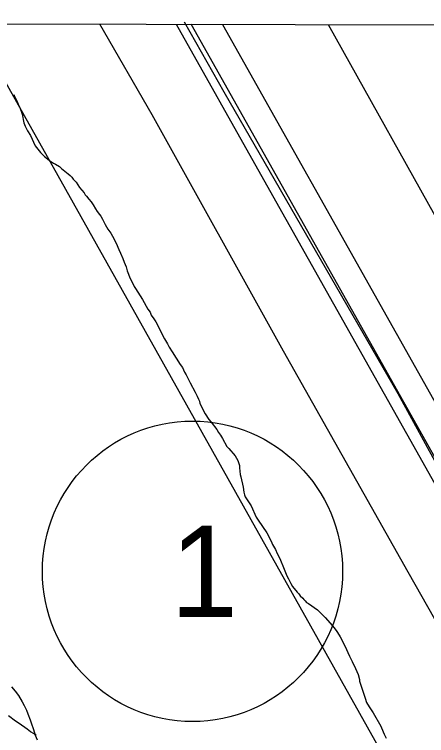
# Model space of a CAD drawing. Extents: x 3177185 to 3215018, y 812988 to 838321.
# Drawn here: x 3185862 to 3186316, y 835794 to 836586 of the extents above; entities that cross this region are included whole.
import ezdxf

# ---------------------------------------------------------------- set-up
doc = ezdxf.new("R2010")
doc.units = 0
for name, color, linetype in [('V-GRID-FRAM', 7, 'Continuous'), ('V-LEVE-TOET', 7, 'Continuous'), ('V-RAIL-TRAK', 7, 'Continuous'), ('V-ROAD-CNTR', 7, 'Continuous'), ('V-ROAD-IDEN', 7, 'Continuous'), ('V-SITE-VEGE', 7, 'Continuous'), ('V-SURV-LINE', 7, 'Continuous'), ('V-TOPO-SHOR', 7, 'Continuous'), ('V-WETL-SWMP', 7, 'Continuous')]:
    doc.layers.add(name, color=color, linetype=linetype)

msp = doc.modelspace()

# ---------------------------------------------------------------- linework, layer by layer
at = {"layer": 'V-GRID-FRAM'}
msp.add_lwpolyline([(3181402.42, 836586.07), (3212801.61, 836513), (3212767.22, 818326.14), (3181352.16, 818399.25), (3181402.42, 836586.07)], dxfattribs=at)
at = {"layer": 'V-LEVE-TOET'}
for points in [[(3187116.25, 834464.44), (3186925.6, 834825.43), (3186860.39, 834954.05), (3186855.88, 834965.58), (3186851.33, 834972.93), (3186814.33, 835039.16), (3186682.24, 835286.96), (3186507.07, 835597.19), (3186375.31, 835833.83), (3186373.07, 835840.52), (3186368.02, 835845.71), (3186295.36, 835973.65), (3186158.41, 836216.39), (3186013.75, 836475.83), (3185956.49, 836575.47)], [(3186207.54, 836574.89), (3186340.46, 836337.21), (3186539.49, 835975.81), (3186717.17, 835666.94), (3186898.65, 835340.5), (3187102.54, 834982.76), (3187266.76, 834701.36), (3187383.23, 834494.39)]]:
    msp.add_lwpolyline(points, dxfattribs=at)
at = {"layer": 'V-RAIL-TRAK'}
msp.add_lwpolyline([(3186040.17, 836575.28), (3186132.96, 836410.73), (3186321.32, 836076.29), (3186480.25, 835793.41), (3186665.13, 835465.53), (3186865.62, 835109.22), (3187040.2, 834800.55), (3187196.12, 834523.53), (3187196.25, 834523.29)], dxfattribs=at)
at = {"layer": 'V-ROAD-CNTR'}
msp.add_lwpolyline([(3186049.16, 836577.87), (3186092.78, 836501.07), (3186284.12, 836169.71), (3186468.4, 835832.88), (3186813.02, 835225.18)], dxfattribs=at)
at = {"layer": 'V-ROAD-IDEN'}
msp.add_circle((3186058.19, 835974.44), 165, dxfattribs=at)
msp.add_circle((3186058.19, 835974.44), 165, dxfattribs=at)
at = {"layer": 'V-SITE-VEGE'}
for p, q in [((3185861.93, 836497.95), (3185862.92, 836495.1)), ((3185862.92, 836495.1), (3185864.94, 836491.2)), ((3185864.94, 836491.2), (3185866.44, 836487.57)), ((3185866.44, 836487.57), (3185868.46, 836483.93)), ((3185868.46, 836483.93), (3185870.95, 836476.67)), ((3185870.95, 836476.67), (3185872.89, 836466.83)), ((3185872.89, 836466.83), (3185874.39, 836463.46)), ((3185874.39, 836463.46), (3185876.91, 836458.27)), ((3185876.91, 836458.27), (3185879.94, 836453.06)), ((3185879.94, 836453.06), (3185885.22, 836441.9)), ((3185885.22, 836441.9), (3185891.06, 836434.33)), ((3185891.06, 836434.33), (3185895.65, 836429.89)), ((3185895.65, 836429.89), (3185902.55, 836424.64)), ((3185902.55, 836424.64), (3185905.37, 836422.79)), ((3185905.37, 836422.79), (3185907.68, 836421.47)), ((3185907.68, 836421.47), (3185912.03, 836419.1)), ((3185912.03, 836419.1), (3185914.33, 836416.74)), ((3185914.33, 836416.74), (3185917.91, 836414.11)), ((3185917.91, 836414.11), (3185921.48, 836410.97)), ((3185921.48, 836410.97), (3185923.78, 836409.14)), ((3185923.78, 836409.14), (3185925.56, 836407.31)), ((3185925.56, 836407.31), (3185927.09, 836405.22)), ((3185927.09, 836405.22), (3185930.15, 836401.83)), ((3185930.15, 836401.83), (3185933.94, 836396.1)), ((3185933.94, 836396.1), (3185939.03, 836390.1)), ((3185939.03, 836390.1), (3185940.29, 836388.01)), ((3185940.29, 836388.01), (3185941.82, 836386.45)), ((3185941.82, 836386.45), (3185944.11, 836383.32)), ((3185944.11, 836383.32), (3185946.65, 836380.19)), ((3185946.65, 836380.19), (3185949.19, 836376.8)), ((3185949.19, 836376.8), (3185951.71, 836372.64)), ((3185951.71, 836372.64), (3185953.48, 836369.52)), ((3185953.48, 836369.52), (3185956.02, 836366.39)), ((3185956.02, 836366.39), (3185957.29, 836364.57)), ((3185957.29, 836364.57), (3185959.31, 836361.19)), ((3185959.31, 836361.19), (3185962.08, 836355.21)), ((3185962.08, 836355.21), (3185965.11, 836350.27)), ((3185965.11, 836350.27), (3185968.41, 836345.84)), ((3185968.41, 836345.84), (3185970.44, 836342.72)), ((3185970.44, 836342.72), (3185974.47, 836334.92)), ((3185974.47, 836334.92), (3185977.22, 836327.92)), ((3185977.22, 836327.92), (3185978.97, 836323.76)), ((3185978.97, 836323.76), (3185981.48, 836318.05)), ((3185981.48, 836318.05), (3185982.98, 836313.9)), ((3185982.98, 836313.9), (3185985.24, 836308.71)), ((3185985.24, 836308.71), (3185986.47, 836304.3)), ((3185986.47, 836304.3), (3185989.72, 836296)), ((3185989.72, 836296), (3185991.24, 836293.66)), ((3185991.24, 836293.66), (3185994.25, 836287.43)), ((3185994.25, 836287.43), (3185995.52, 836285.09)), ((3185995.52, 836285.09), (3185998.3, 836280.92)), ((3185998.3, 836280.92), (3186003.37, 836272.85)), ((3186003.37, 836272.85), (3186009.17, 836262.2)), ((3186009.17, 836262.2), (3186011.71, 836259.06)), ((3186011.71, 836259.06), (3186012.96, 836255.95)), ((3186012.96, 836255.95), (3186015.75, 836251.79)), ((3186015.75, 836251.79), (3186017.77, 836248.4)), ((3186017.77, 836248.4), (3186023.31, 836238.01)), ((3186023.31, 836238.01), (3186025.33, 836233.85)), ((3186025.33, 836233.85), (3186027.6, 836229.69)), ((3186027.6, 836229.69), (3186030.63, 836224.49)), ((3186030.63, 836224.49), (3186032.39, 836220.59)), ((3186032.39, 836220.59), (3186035.94, 836215.65)), ((3186035.94, 836215.65), (3186044.8, 836201.59)), ((3186044.8, 836201.59), (3186047.08, 836198.21)), ((3186047.08, 836198.21), (3186049.59, 836193.27)), ((3186049.59, 836193.27), (3186051.36, 836190.15)), ((3186051.36, 836190.15), (3186053.63, 836185.73)), ((3186053.63, 836185.73), (3186055.64, 836181.32)), ((3186055.64, 836181.32), (3186061.19, 836171.18)), ((3186061.19, 836171.18), (3186063.45, 836166.76)), ((3186063.45, 836166.76), (3186064.7, 836163.65)), ((3186064.7, 836163.65), (3186065.97, 836161.31)), ((3186065.97, 836161.31), (3186066.45, 836158.72)), ((3186066.45, 836158.72), (3186072.25, 836147.55)), ((3186072.25, 836147.55), (3186076.3, 836141.3)), ((3186076.3, 836141.3), (3186078.58, 836138.18)), ((3186078.58, 836138.18), (3186084.93, 836130.09)), ((3186084.93, 836130.09), (3186086.7, 836126.97)), ((3186086.7, 836126.97), (3186088.98, 836124.1)), ((3186088.98, 836124.1), (3186091.26, 836120.46)), ((3186091.26, 836120.46), (3186096.05, 836111.62)), ((3186096.05, 836111.62), (3186098.09, 836109.53)), ((3186098.09, 836109.53), (3186104.96, 836101.44)), ((3186104.96, 836101.44), (3186107.99, 836096.24)), ((3186107.99, 836096.24), (3186109.99, 836090.79)), ((3186109.99, 836090.79), (3186109.95, 836087.95)), ((3186109.95, 836087.95), (3186110.63, 836080.72)), ((3186110.63, 836080.72), (3186111.37, 836078.13)), ((3186111.37, 836078.13), (3186113.81, 836066.73)), ((3186113.81, 836066.73), (3186114.52, 836061.56)), ((3186114.52, 836061.56), (3186115.25, 836058.46)), ((3186115.25, 836058.46), (3186116, 836056.38)), ((3186116, 836056.38), (3186122.58, 836046.23)), ((3186122.58, 836046.23), (3186128.36, 836033.77)), ((3186128.36, 836033.77), (3186130.39, 836030.64)), ((3186130.39, 836030.64), (3186139.77, 836016.84)), ((3186139.77, 836016.84), (3186144.55, 836007.49)), ((3186144.55, 836007.49), (3186146.31, 836003.85)), ((3186146.31, 836003.85), (3186149.6, 835998.39)), ((3186149.6, 835998.39), (3186151.35, 835994.23)), ((3186151.35, 835994.23), (3186154.12, 835988.52)), ((3186154.12, 835988.52), (3186159.13, 835976.84)), ((3186159.13, 835976.84), (3186161.88, 835969.58)), ((3186161.88, 835969.58), (3186163.65, 835966.2)), ((3186163.65, 835966.2), (3186166.16, 835961)), ((3186166.16, 835961), (3186168.19, 835957.88)), ((3186168.19, 835957.88), (3186173.27, 835951.62)), ((3186173.27, 835951.62), (3186175.05, 835949.79)), ((3186175.05, 835949.79), (3186176.57, 835947.71)), ((3186176.57, 835947.71), (3186179.38, 835945.09)), ((3186179.38, 835945.09), (3186180.65, 835943.52)), ((3186180.65, 835943.52), (3186182.18, 835941.96)), ((3186182.18, 835941.96), (3186183.45, 835940.39)), ((3186183.45, 835940.39), (3186185.76, 835939.07)), ((3186185.76, 835939.07), (3186195.48, 835932.23)), ((3186195.48, 835932.23), (3186199.82, 835928.31)), ((3186199.82, 835928.31), (3186204.15, 835923.86)), ((3186204.15, 835923.86), (3186212.29, 835914.47)), ((3186212.29, 835914.47), (3186213.56, 835912.64)), ((3186213.56, 835912.64), (3186216.1, 835909.51)), ((3186216.1, 835909.51), (3186217.62, 835907.17)), ((3186217.62, 835907.17), (3186220.4, 835902.49)), ((3186220.4, 835902.49), (3186225.7, 835892.61)), ((3186225.7, 835892.61), (3186230.71, 835881.19)), ((3186230.71, 835881.19), (3186233.74, 835875.47)), ((3186233.74, 835875.47), (3186237.52, 835867.94)), ((3186237.52, 835867.94), (3186240.27, 835861.19)), ((3186240.27, 835861.19), (3186241.75, 835855.75)), ((3186241.75, 835855.75), (3186241.98, 835853.68)), ((3186241.98, 835853.68), (3186247.94, 835835.02)), ((3186247.94, 835835.02), (3186249.69, 835830.35)), ((3186249.69, 835830.35), (3186252.47, 835825.67)), ((3186252.47, 835825.67), (3186256.77, 835819.16)), ((3186256.77, 835819.16), (3186265.1, 835804.34)), ((3185863.49, 835810.02), (3185856, 835815.66)), ((3185867.49, 835807.44), (3185863.49, 835810.02)), ((3185876.49, 835801.28), (3185867.49, 835807.44)), ((3186265.1, 835804.34), (3186267.87, 835798.36)), ((3185879.98, 835798.21), (3185876.49, 835801.28)), ((3185883.99, 835796.14), (3185879.98, 835798.21)), ((3185886.49, 835794.09), (3185883.99, 835796.14)), ((3186267.87, 835798.36), (3186268.86, 835795.51)), ((3186268.86, 835795.51), (3186271.13, 835791.35))]:
    msp.add_line(p, q, dxfattribs=at)
at = {"layer": 'V-SURV-LINE'}
for points in [[(3186637.84, 835543.47), (3186056.9, 836575.24)], [(3186091.37, 836575.16), (3186663.99, 835558.18)]]:
    msp.add_lwpolyline(points, dxfattribs=at)
at = {"layer": 'V-TOPO-SHOR'}
msp.add_lwpolyline([(3185818.79, 836570.95), (3186715.05, 834976.3), (3186800.1, 834939.44), (3186819.81, 834836.62), (3187764.4, 833190.61), (3187867.38, 832974.26), (3188193.3, 832392.27), (3188600.69, 831693.89)], dxfattribs=at)
at = {"layer": 'V-WETL-SWMP'}
msp.add_lwpolyline([(3185859.07, 835847.45), (3185863.4, 835843.01), (3185866.95, 835838.06), (3185870.99, 835831.04), (3185873.01, 835827.14), (3185875.78, 835821.94), (3185877.28, 835818.05), (3185879.77, 835811.31), (3185880.77, 835808.2), (3185883.52, 835800.93), (3185885.24, 835794.46), (3185887.5, 835789.53)], dxfattribs=at)

# ---------------------------------------------------------------- texts
at = {"layer": 'V-ROAD-IDEN'}
msp.add_text('1', height=100, rotation=359.99998, dxfattribs=at).set_placement((3186033.78, 835924.44))

doc.saveas('drawing.dxf')
